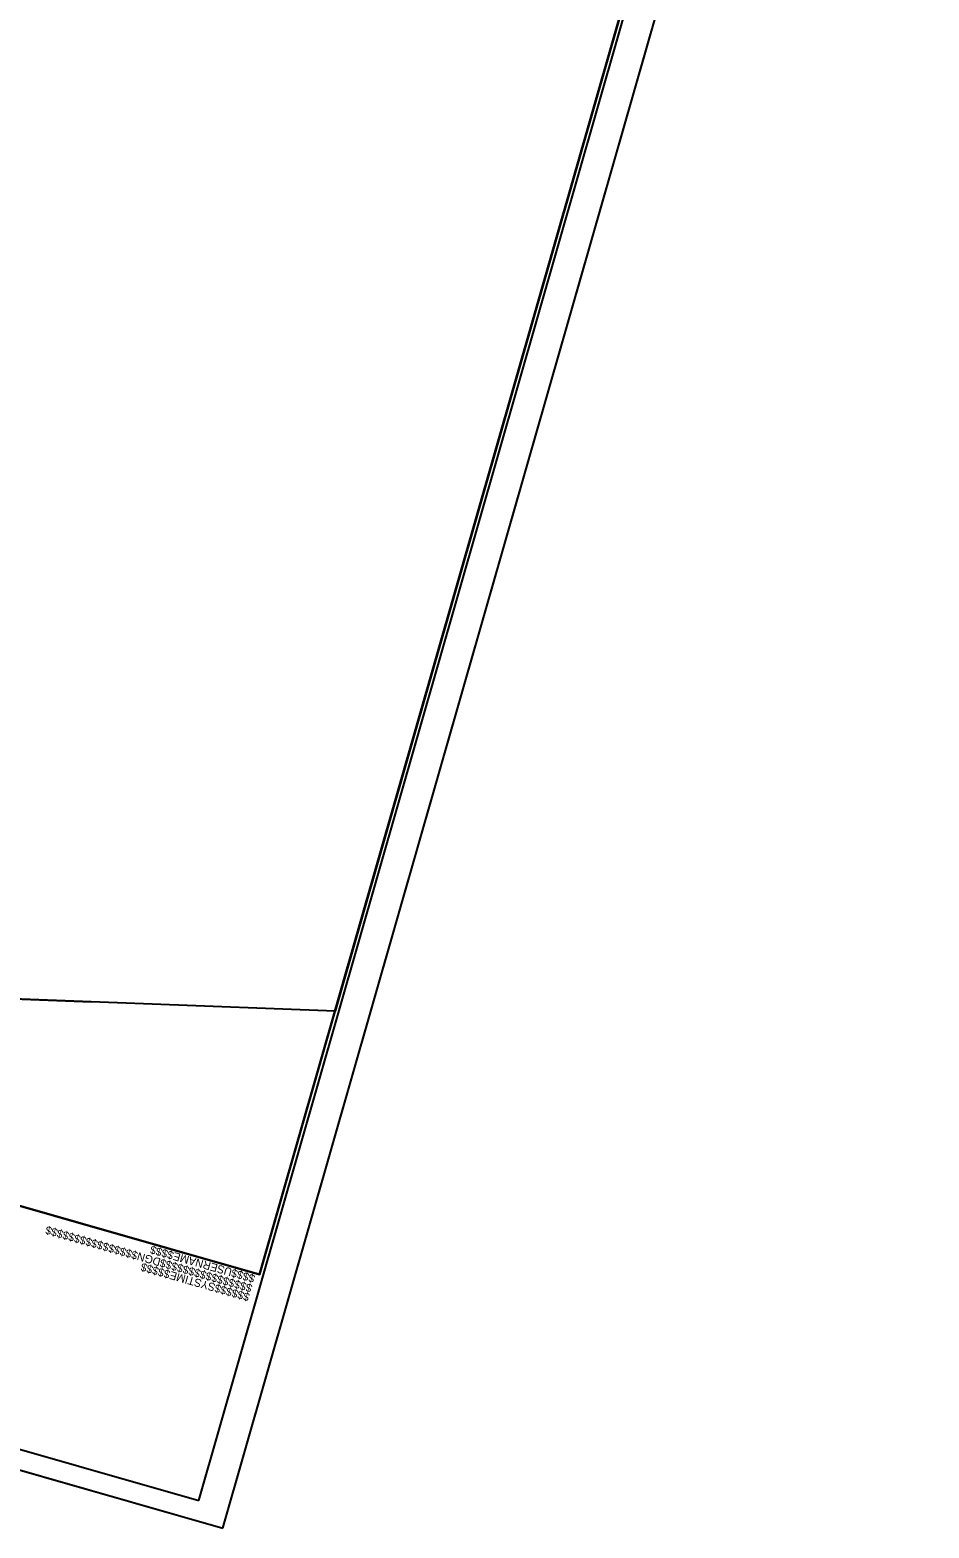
# Model space of a CAD drawing. Extents: x 2096934 to 2098492, y 687716 to 689682.
# Drawn here: x 2097902 to 2098492, y 687716 to 688699 of the extents above; entities that cross this region are included whole.
import ezdxf

# ---------------------------------------------------------------- set-up
doc = ezdxf.new("R2010")
doc.units = 0
for name, color, linetype in [('Prop Drainage Structure Catch Basin Grate 840 03F CELL', 7, 'Continuous'), ('Prop Drainage Structure Drop Inlet Grate 2 Narrow Slots and Flat Grates 840 29 CELL', 7, 'Continuous'), ('Prop Drainage Structure Outlet Generic CELL', 7, 'Continuous'), ('Prop Drainage Structure Plot Symbol 20 Scale', 7, 'Continuous'), ('Scratch_Level_3', 7, 'Continuous'), ('Sheet Clip Boundary CELL', 7, 'Continuous')]:
    doc.layers.add(name, color=color, linetype=linetype)

msp = doc.modelspace()

# ---------------------------------------------------------------- linework, layer by layer
at = {"layer": 'Prop Drainage Structure Catch Basin Grate 840 03F CELL'}
for p, q in [((2098028.44, 687715.97), (2098491.74, 689334.46)), ((2096975.72, 688017.32), (2098028.44, 687715.97))]:
    msp.add_line(p, q, dxfattribs=at)
at = {"layer": 'Prop Drainage Structure Drop Inlet Grate 2 Narrow Slots and Flat Grates 840 29 CELL'}
msp.add_line((2097592.68, 688074.63), (2097942.42, 688061.22), dxfattribs=at)
at = {"layer": 'Prop Drainage Structure Outlet Generic CELL'}
msp.add_lwpolyline([(2098028.44, 687715.97), (2098491.74, 689334.46), (2097439.02, 689635.81), (2096975.72, 688017.32)], close=True, dxfattribs=at)
at = {"layer": 'Prop Drainage Structure Plot Symbol 20 Scale'}
msp.add_lwpolyline([(2098012.79, 687733.97), (2098471.26, 689335.63), (2097457.01, 689625.98), (2096998.53, 688024.31)], close=True, dxfattribs=at)
at = {"layer": 'Scratch_Level_3'}
msp.add_line((2098052.61, 687882.22), (2098052.61, 687882.22), dxfattribs=at)
for points in [[(2097455.97, 689613.3), (2097043.16, 688171.19), (2098052.61, 687882.22), (2098465.42, 689324.31)], [(2098052.61, 687882.22), (2097043.17, 688171.15), (2097400.9, 689420.95), (2097545.17, 689379.67), (2097600.23, 689571.98), (2098465.42, 689324.31)]]:
    msp.add_lwpolyline(points, close=True, dxfattribs=at)
at = {"layer": 'Sheet Clip Boundary CELL'}
for points in [[(2098102.1, 688055.1), (2097347.73, 688084.03), (2097043.16, 688171.19), (2097346.07, 689229.4), (2097355.46, 689262.19), (2097400.9, 689420.95), (2097628.1, 689355.93), (2097683.15, 689548.26), (2098465.42, 689324.31)], [(2098102.1, 688055.1), (2097347.73, 688084.03), (2097043.16, 688171.19), (2097345.95, 689228.93), (2097355.46, 689262.19), (2097400.91, 689420.95), (2097628.1, 689355.93), (2097683.15, 689548.26), (2098465.42, 689324.31)]]:
    msp.add_lwpolyline(points, close=True, dxfattribs=at)

# ---------------------------------------------------------------- texts
at = {"layer": 'Scratch_Level_3'}
for s, p in [('$$$$$$$$$$$$$$$$DGN$$$$$$$$$$$$$$$$', (2098048.24, 687875.53)), ('$$$$USERNAME$$$$', (2098050.03, 687881.83)), ('$$$$$$SYSTIME$$$$$', (2098046.59, 687869.68))]:
    msp.add_text(s, height=5.25, rotation=164.02589, dxfattribs=at).set_placement(p)

doc.saveas('drawing.dxf')
